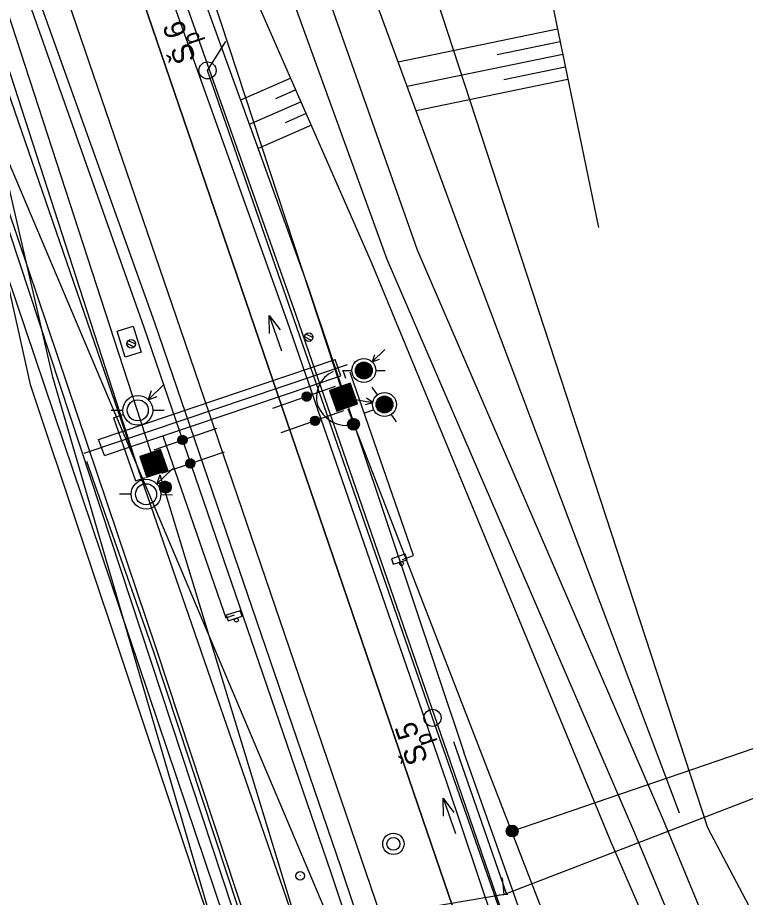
# Model space of a CAD drawing. Extents: x -439815 to -439102, y -1131353 to -1129707.
# Drawn here: x -439341.3 to -439298.8, y -1130686.6 to -1130635.3 of the extents above; entities that cross this region are included whole.
import ezdxf

# ---------------------------------------------------------------- set-up
doc = ezdxf.new("R2010")
doc.units = 0
for name, color, linetype in [('Level 1', 7, 'Continuous'), ('Level 10', 7, 'Continuous'), ('Level 11', 7, 'Continuous'), ('Level 14', 7, 'Continuous'), ('Level 15', 7, 'Continuous'), ('Level 2', 7, 'Continuous'), ('Level 20', 7, 'Continuous'), ('Level 36', 7, 'Continuous'), ('Level 4', 7, 'Continuous'), ('Level 42', 7, 'Continuous'), ('Level 48', 7, 'Continuous'), ('Level 49', 7, 'Continuous'), ('Level 5', 7, 'Continuous'), ('Level 57', 7, 'Continuous'), ('Level 59', 7, 'Continuous'), ('Level 6', 7, 'Continuous'), ('Level 61', 7, 'Continuous'), ('Level 62', 7, 'Continuous'), ('Level 63', 7, 'Continuous'), ('Level 7', 7, 'Continuous'), ('Level 9', 7, 'Continuous')]:
    doc.layers.add(name, color=color, linetype=linetype)

# ---------------------------------------------------------------- blocks, each defined once
blk = doc.blocks.new('KOTV_T')
at = {"layer": 'Level 1'}
for p, q in [((-3.44, -0.33), (0.33, 3.44)), ((-3.42, 0.47), (-0.47, 3.42)), ((-3.31, -0.98), (0.98, 3.31)), ((-3.09, -1.54), (1.54, 3.09)), ((-3.06, 1.61), (-1.61, 3.06)), ((-2.8, -2.02), (2.02, 2.8)), ((-2.44, -2.44), (2.44, 2.44)), ((-2.02, -2.8), (2.8, 2.02)), ((-1.54, -3.09), (3.09, 1.54)), ((-0.98, -3.31), (3.31, 0.98)), ((-0.33, -3.44), (3.44, 0.33)), ((0.47, -3.42), (3.42, -0.47)), ((1.61, -3.06), (3.06, -1.61))]:
    blk.add_line(p, q, dxfattribs=at)
blk.add_circle((0, 0), 3.45, dxfattribs=at)
blk = doc.blocks.new('ST1K_K')
at = {"layer": 'Level 1'}
for p, q in [((0, 0), (45.31, 0)), ((20.84, -3.13), (17.41, 0.3)), ((21.43, -3.01), (17.53, 0.89)), ((21.94, -2.81), (17.73, 1.4)), ((22.38, -2.55), (17.99, 1.84)), ((22.76, -2.22), (18.32, 2.22)), ((23.08, -1.84), (18.7, 2.55)), ((23.35, -1.4), (19.14, 2.81)), ((23.55, -0.89), (19.65, 3.01)), ((23.67, -0.3), (20.24, 3.13)), ((23.65, 0.42), (20.96, 3.11)), ((23.32, 1.46), (22, 2.78)), ((20.12, -3.11), (17.43, -0.42)), ((19.07, -2.78), (17.76, -1.46))]:
    blk.add_line(p, q, dxfattribs=at)
blk.add_circle((20.54, 0), 3.14, dxfattribs=at)
blk = doc.blocks.new('ST_BP')
at = {"layer": 'Level 1'}
for p, q in [((7.5, 7.5), (-7.5, 7.5)), ((-7.5, 7.5), (-7.5, -7.5)), ((-7.5, -7.5), (7.5, 7.5)), ((-7.5, -7.08), (7.08, 7.5)), ((-7.5, -6.65), (6.65, 7.5)), ((-7.5, -6.23), (6.23, 7.5)), ((-7.5, -5.8), (5.8, 7.5)), ((-7.5, -5.38), (5.38, 7.5)), ((-7.5, -4.95), (4.95, 7.5)), ((-7.5, -4.53), (4.53, 7.5)), ((-7.5, -4.11), (4.11, 7.5)), ((-7.5, -3.68), (3.68, 7.5)), ((-7.5, -3.26), (3.26, 7.5)), ((-7.5, -2.83), (2.83, 7.5)), ((-7.5, -2.41), (2.41, 7.5)), ((-7.5, -1.98), (1.98, 7.5)), ((-7.5, -1.56), (1.56, 7.5)), ((-7.5, -1.14), (1.14, 7.5)), ((-7.5, -0.71), (0.71, 7.5)), ((-7.5, -0.29), (0.29, 7.5)), ((-7.5, 0.14), (-0.14, 7.5)), ((-7.5, 0.56), (-0.56, 7.5)), ((-7.5, 0.99), (-0.99, 7.5)), ((-7.5, 1.41), (-1.41, 7.5)), ((-7.5, 1.83), (-1.83, 7.5)), ((-7.5, 2.26), (-2.26, 7.5)), ((-7.5, 2.68), (-2.68, 7.5)), ((-7.5, 3.11), (-3.11, 7.5)), ((-7.5, 3.53), (-3.53, 7.5)), ((-7.5, 3.96), (-3.96, 7.5)), ((-7.5, 4.38), (-4.38, 7.5)), ((-7.5, 4.8), (-4.8, 7.5)), ((-7.5, 5.23), (-5.23, 7.5)), ((-7.5, 5.65), (-5.65, 7.5)), ((-7.5, 6.08), (-6.08, 7.5)), ((-7.5, 6.5), (-6.5, 7.5)), ((-7.5, 6.92), (-6.92, 7.5)), ((-7.5, 7.35), (-7.35, 7.5)), ((-7.08, -7.5), (7.5, 7.08)), ((-6.65, -7.5), (7.5, 6.65)), ((-6.23, -7.5), (7.5, 6.23)), ((7.5, -7.5), (7.5, 7.5)), ((-5.8, -7.5), (7.5, 5.8)), ((-5.38, -7.5), (7.5, 5.38)), ((-4.95, -7.5), (7.5, 4.95)), ((-4.53, -7.5), (7.5, 4.53)), ((-4.11, -7.5), (7.5, 4.11)), ((-3.68, -7.5), (7.5, 3.68)), ((-3.26, -7.5), (7.5, 3.26)), ((-2.83, -7.5), (7.5, 2.83)), ((-2.41, -7.5), (7.5, 2.41)), ((-1.98, -7.5), (7.5, 1.98)), ((-1.56, -7.5), (7.5, 1.56)), ((-1.14, -7.5), (7.5, 1.14)), ((-0.71, -7.5), (7.5, 0.71)), ((-0.29, -7.5), (7.5, 0.29)), ((0.14, -7.5), (7.5, -0.14)), ((0.56, -7.5), (7.5, -0.56)), ((0.99, -7.5), (7.5, -0.99)), ((1.41, -7.5), (7.5, -1.41)), ((1.83, -7.5), (7.5, -1.83)), ((2.26, -7.5), (7.5, -2.26)), ((2.68, -7.5), (7.5, -2.68)), ((3.11, -7.5), (7.5, -3.11)), ((3.53, -7.5), (7.5, -3.53)), ((3.96, -7.5), (7.5, -3.96)), ((4.38, -7.5), (7.5, -4.38)), ((4.8, -7.5), (7.5, -4.8)), ((5.23, -7.5), (7.5, -5.23)), ((5.65, -7.5), (7.5, -5.65)), ((-7.5, -7.5), (7.5, -7.5)), ((6.08, -7.5), (7.5, -6.08)), ((6.5, -7.5), (7.5, -6.5)), ((6.92, -7.5), (7.5, -6.92)), ((7.35, -7.5), (7.5, -7.35))]:
    blk.add_line(p, q, dxfattribs=at)

msp = doc.modelspace()

# ---------------------------------------------------------------- linework, layer by layer
at = {"layer": 'Level 10'}
for p, q in [((-439309.738, -1130635.982), (-439319.036, -1130637.898)), ((-439309.588, -1130636.718), (-439313.262, -1130637.474)), ((-439309.436, -1130637.452), (-439318.514, -1130639.322)), ((-439309.286, -1130638.186), (-439312.872, -1130638.926)), ((-439325.316, -1130638.834), (-439328.242, -1130640.118)), ((-439309.134, -1130638.922), (-439317.992, -1130640.746)), ((-439325.014, -1130639.522), (-439326.204, -1130640.044)), ((-439324.712, -1130640.21), (-439327.732, -1130641.534)), ((-439324.412, -1130640.896), (-439325.636, -1130641.434)), ((-439324.11, -1130641.582), (-439327.22, -1130642.946))]:
    msp.add_line(p, q, dxfattribs=at)
at = {"layer": 'Level 11'}
for points in [[(-439303.556, -1130682.146), (-439317.916, -1130648.878), (-439327.804, -1130620.82), (-439331.376, -1130615.792)], [(-439331.216, -1130618.836), (-439329.76, -1130621.648), (-439319.704, -1130649.398), (-439305.298, -1130682.74)], [(-439290.368, -1130714.13), (-439303.556, -1130682.146)], [(-439305.298, -1130682.74), (-439291.93, -1130714.86)]]:
    msp.add_lwpolyline(points, dxfattribs=at)
at = {"layer": 'Level 14'}
msp.add_lwpolyline([(-439335.44, -1130653.596), (-439334.502, -1130653.304), (-439334.034, -1130654.828), (-439334.97, -1130655.116), (-439335.44, -1130653.596)], dxfattribs=at)
at = {"layer": 'Level 15'}
for p, q in [((-439324.102, -1130654.142), (-439324.512, -1130653.94)), ((-439324.016, -1130653.974), (-439324.432, -1130653.77)), ((-439334.46, -1130654.528), (-439334.87, -1130654.328)), ((-439334.374, -1130654.362), (-439334.79, -1130654.158))]:
    msp.add_line(p, q, dxfattribs=at)
for centre in [(-439334.622, -1130654.34), (-439324.264, -1130653.954)]:
    msp.add_circle(centre, 0.25, dxfattribs=at)
at = {"layer": 'Level 2'}
for centre, radius, start, end in [((-439322.18, -1130657.459), 1.636, 113.691, 198.3072), ((-439322.18, -1130657.459), 1.636, 113.691, 198.3072), ((-439321.987, -1130657.207), 1.907, 203.6959, 268.8931), ((-439321.987, -1130657.207), 1.907, 203.6959, 268.8931)]:
    msp.add_arc(centre, radius, start, end, dxfattribs=at)
at = {"layer": 'Level 20'}
for points in [[(-439317.356, -1130682.842), (-439326.906, -1130654.872), (-439337.798, -1130622.974), (-439339.224, -1130618.794), (-439340.706, -1130614.468), (-439349.146, -1130589.75), (-439360.302, -1130557.13), (-439371.172, -1130525.358), (-439381.62, -1130494.81), (-439392.342, -1130463.488), (-439403.314, -1130431.488), (-439413.424, -1130401.962), (-439423.826, -1130371.538), (-439434.464, -1130340.548), (-439445.064, -1130309.558), (-439445.462, -1130308.388), (-439447.35, -1130302.89), (-439457.16, -1130275.562)], [(-439321.24, -1130684.25), (-439331.724, -1130653.514), (-439341.682, -1130624.428), (-439343.148, -1130620.102), (-439344.652, -1130615.74), (-439353.044, -1130591.112), (-439364.316, -1130558.138), (-439374.988, -1130526.952), (-439385.508, -1130496.17), (-439396.186, -1130464.956), (-439407.226, -1130432.678), (-439417.232, -1130403.478), (-439427.682, -1130373.028), (-439438.464, -1130341.588), (-439448.942, -1130311.012), (-439450.914, -1130305.246), (-439460.972, -1130277.082)], [(-439269.22, -1130818.812), (-439281.814, -1130783.396), (-439292.526, -1130753.502), (-439304.678, -1130719.318), (-439314.858, -1130690.108), (-439317.356, -1130682.842)], [(-439286.854, -1130785.132), (-439297.084, -1130755.104), (-439308.786, -1130720.798), (-439319.098, -1130690.52), (-439321.24, -1130684.25)]]:
    msp.add_lwpolyline(points, dxfattribs=at)
at = {"layer": 'Level 36'}
for p, q in [((-439322.55, -1130616.62), (-439300.99, -1130682.56)), ((-439323.66, -1130704.2), (-439346.85, -1130635.55)), ((-439300.99, -1130682.56), (-439292.55, -1130698.49))]:
    msp.add_line(p, q, dxfattribs=at)
at = {"layer": 'Level 4'}
for points in [[(-439316.204, -1130679.942), (-439325.518, -1130652.992), (-439336.244, -1130623.018), (-439338.082, -1130617.638)], [(-439315.982, -1130678.73), (-439324.99, -1130652.666), (-439335.578, -1130622.688), (-439337.526, -1130617.51)], [(-439322.95, -1130685.206), (-439333.858, -1130653.394), (-439343.59, -1130625.92), (-439345.752, -1130619.412)], [(-439322.368, -1130684.93), (-439333.25, -1130653.118), (-439343.108, -1130625.602), (-439345.194, -1130619.284)], [(-439280.01, -1130783.522), (-439290.374, -1130752.75), (-439302.642, -1130717.624), (-439315.982, -1130678.73)], [(-439280.01, -1130783.522), (-439291.102, -1130753.178), (-439303.358, -1130718.188), (-439316.204, -1130679.942)], [(-439237.656, -1130937.666), (-439241, -1130926.51), (-439249.718, -1130901.172), (-439258.406, -1130875.05), (-439266.76, -1130849.346), (-439276.348, -1130820.732), (-439289.274, -1130782.246), (-439298.276, -1130755.542), (-439309.968, -1130722.042), (-439322.368, -1130684.93)], [(-439237.656, -1130937.666), (-439241.95, -1130926.674), (-439250.188, -1130901.72), (-439259.018, -1130875.526), (-439267.634, -1130849.508), (-439276.91, -1130821.49), (-439290.192, -1130781.67), (-439298.758, -1130756.05), (-439310.466, -1130722.552), (-439322.95, -1130685.206)]]:
    msp.add_lwpolyline(points, dxfattribs=at)
at = {"layer": 'Level 42'}
for points in [[(-439395.105, -1130455.427), (-439392.342, -1130463.488), (-439381.62, -1130494.81), (-439371.172, -1130525.358), (-439360.302, -1130557.13), (-439349.146, -1130589.75), (-439340.706, -1130614.468), (-439339.224, -1130618.794), (-439337.798, -1130622.974), (-439326.906, -1130654.872), (-439317.356, -1130682.842)], [(-439321.24, -1130684.25), (-439331.724, -1130653.514), (-439341.682, -1130624.428), (-439343.148, -1130620.102), (-439344.652, -1130615.74), (-439353.044, -1130591.112), (-439364.316, -1130558.138), (-439374.988, -1130526.952), (-439385.508, -1130496.17), (-439396.186, -1130464.956), (-439399.158, -1130456.267)], [(-439317.356, -1130682.842), (-439314.858, -1130690.108), (-439304.678, -1130719.318), (-439294.356, -1130748.353)], [(-439299.143, -1130749.065), (-439308.786, -1130720.798), (-439319.098, -1130690.52), (-439321.24, -1130684.25)]]:
    msp.add_lwpolyline(points, dxfattribs=at)
at = {"layer": 'Level 48'}
msp.add_line((-439330.171, -1130638.383), (-439329.092, -1130636.695), dxfattribs=at)
msp.add_lwpolyline([(-439273.977, -1130800.586), (-439287.398, -1130761.145), (-439303.815, -1130713.917), (-439317.04, -1130676.167), (-439330.171, -1130638.383)], dxfattribs=at)
for centre in [(-439330.171, -1130638.383), (-439317.04, -1130676.167)]:
    msp.add_circle(centre, 0.5, dxfattribs=at)
at = {"layer": 'Level 49'}
for p, q in [((-439326.571, -1130652.681), (-439325.854, -1130654.756)), ((-439316.418, -1130680.852), (-439315.701, -1130682.928))]:
    msp.add_line(p, q, dxfattribs=at)
for points in [[(-439326.552, -1130653.732), (-439326.571, -1130652.681), (-439325.937, -1130653.52)], [(-439316.399, -1130681.904), (-439316.418, -1130680.852), (-439315.785, -1130681.691)]]:
    msp.add_lwpolyline(points, dxfattribs=at)
at = {"layer": 'Level 5'}
msp.add_lwpolyline([(-439277.797, -1130823.31), (-439296.36, -1130772.17), (-439314.646, -1130718.277), (-439334.211, -1130661.631), (-439352.883, -1130603.988)], dxfattribs=at)
at = {"layer": 'Level 57'}
for p, q in [((-439300.573, -1130713.355), (-439321.952, -1130658.15)), ((-439315.693, -1130718.482), (-439332.927, -1130662.012)), ((-439312.411, -1130682.787), (-439281.025, -1130672.03))]:
    msp.add_line(p, q, dxfattribs=at)
at = {"layer": 'Level 59'}
for p, q in [((-439322.958, -1130688.178), (-439346.578, -1130632.414)), ((-439315.822, -1130677.544), (-439312.712, -1130686.468)), ((-439312.712, -1130686.468), (-439322.958, -1130688.178))]:
    msp.add_line(p, q, dxfattribs=at)
msp.add_lwpolyline([(-439240.615, -1130935.08), (-439245.006, -1130936.575), (-439254.477, -1130905.195), (-439274.831, -1130847.058), (-439298.026, -1130780.807), (-439307.773, -1130752.965), (-439314.372, -1130732.153), (-439325.758, -1130696.243), (-439342.929, -1130644.213), (-439353.367, -1130615.721)], dxfattribs=at)
at = {"layer": 'Level 6'}
for p, q in [((-439312.884, -1130686.484), (-439276.288, -1130672.354)), ((-439312.972, -1130685.498), (-439312.884, -1130686.484)), ((-439313.134, -1130686.506), (-439312.636, -1130686.462))]:
    msp.add_line(p, q, dxfattribs=at)
at = {"layer": 'Level 61'}
for p, q in [((-439322.281, -1130657.205), (-439341.23, -1130599.505)), ((-439352.156, -1130603.174), (-439333.292, -1130661.29))]:
    msp.add_line(p, q, dxfattribs=at)
at = {"layer": 'Level 62'}
msp.add_line((-439334.327, -1130661.321), (-439354.141, -1130603.913), dxfattribs=at)
at = {"layer": 'Level 63'}
for p, q in [((-439337.379, -1130660.728), (-439322, -1130655.537)), ((-439336.54, -1130659.917), (-439322.722, -1130655.253)), ((-439322.397, -1130656.198), (-439322.722, -1130655.253)), ((-439321.46, -1130655.63), (-439320.64, -1130655.63)), ((-439321.41, -1130655.565), (-439320.689, -1130655.565)), ((-439321.328, -1130655.499), (-439320.771, -1130655.499)), ((-439321.214, -1130655.434), (-439320.886, -1130655.434)), ((-439322.094, -1130656.36), (-439322.257, -1130655.887)), ((-439318.154, -1130666.701), (-439321.84, -1130656.011)), ((-439321.541, -1130655.893), (-439320.558, -1130655.893)), ((-439321.525, -1130655.827), (-439320.575, -1130655.827)), ((-439321.525, -1130655.958), (-439320.575, -1130655.958)), ((-439321.509, -1130655.761), (-439320.591, -1130655.761)), ((-439321.509, -1130656.024), (-439320.591, -1130656.024)), ((-439321.492, -1130655.696), (-439320.608, -1130655.696)), ((-439321.492, -1130656.089), (-439320.608, -1130656.089)), ((-439321.46, -1130656.155), (-439320.64, -1130656.155)), ((-439336.192, -1130660.855), (-439322.397, -1130656.198)), ((-439321.41, -1130656.22), (-439320.689, -1130656.22)), ((-439321.328, -1130656.286), (-439320.771, -1130656.286)), ((-439321.214, -1130656.351), (-439320.886, -1130656.351)), ((-439319.823, -1130658.367), (-439320.293, -1130657.696)), ((-439319.751, -1130658.357), (-439320.258, -1130657.632)), ((-439319.687, -1130658.332), (-439320.214, -1130657.581)), ((-439319.624, -1130658.308), (-439320.169, -1130657.53)), ((-439319.561, -1130658.284), (-439320.125, -1130657.479)), ((-439319.517, -1130658.233), (-439320.062, -1130657.455)), ((-439319.473, -1130658.182), (-439319.999, -1130657.431)), ((-439319.428, -1130658.131), (-439319.936, -1130657.406)), ((-439319.394, -1130658.067), (-439319.863, -1130657.396)), ((-439319.368, -1130657.989), (-439319.782, -1130657.398)), ((-439319.361, -1130657.884), (-439319.681, -1130657.428)), ((-439319.373, -1130657.753), (-439319.561, -1130657.484)), ((-439321.029, -1130658.386), (-439320.434, -1130658.181)), ((-439320.006, -1130658.335), (-439320.325, -1130657.879)), ((-439319.905, -1130658.365), (-439320.318, -1130657.774)), ((-439320.125, -1130658.279), (-439320.313, -1130658.01)), ((-439335.649, -1130658.654), (-439335.093, -1130658.462)), ((-439336.192, -1130660.855), (-439336.54, -1130659.917)), ((-439334.379, -1130662.341), (-439333.793, -1130662.139)), ((-439318.797, -1130666.923), (-439318.154, -1130666.701))]:
    msp.add_line(p, q, dxfattribs=at)
for points in [[(-439292.524, -1130791.32), (-439307.367, -1130752.78), (-439315.541, -1130727.251), (-439322.482, -1130704.449), (-439333.14, -1130672.167), (-439347.586, -1130629.381), (-439352.159, -1130615.872), (-439360.579, -1130591.518), (-439378.343, -1130536.883), (-439390.124, -1130502.75), (-439400.777, -1130471.095), (-439412.393, -1130437.172), (-439439.873, -1130358.662), (-439450.355, -1130327.185), (-439449.866, -1130322.123), (-439455.753, -1130305.502), (-439457.3, -1130298.85), (-439459.497, -1130292.207)], [(-439319.821, -1130654.664), (-439320.557, -1130655.399)], [(-439320.421, -1130654.983), (-439320.557, -1130655.399)], [(-439320.557, -1130655.399), (-439320.141, -1130655.244)], [(-439322.289, -1130655.893), (-439321.746, -1130655.893)], [(-439320.354, -1130655.893), (-439319.811, -1130655.893)], [(-439332.705, -1130656.685), (-439333.625, -1130657.605)], [(-439333.455, -1130657.084), (-439333.625, -1130657.605)], [(-439320.243, -1130657.311), (-439320.554, -1130656.867)], [(-439333.625, -1130657.605), (-439333.105, -1130657.41)], [(-439321.555, -1130657.58), (-439320.53, -1130657.76)], [(-439320.53, -1130657.76), (-439320.896, -1130657.509)], [(-439335.79, -1130658.221), (-439335.112, -1130658.221)], [(-439333.371, -1130658.221), (-439332.693, -1130658.221)], [(-439320.949, -1130657.888), (-439320.53, -1130657.76)], [(-439335.649, -1130658.654), (-439334.379, -1130662.341)], [(-439319.133, -1130658.896), (-439319.444, -1130658.452)], [(-439332.774, -1130659.701), (-439329.416, -1130669.439), (-439329.105, -1130670.34), (-439328.594, -1130670.164)], [(-439229.706, -1130961.083), (-439234.319, -1130947.462), (-439238.472, -1130936.844), (-439247.924, -1130921.561), (-439263.264, -1130880.523), (-439279.451, -1130829.598), (-439292.591, -1130791.38), (-439307.551, -1130752.883), (-439315.726, -1130727.354), (-439322.667, -1130704.552), (-439333.324, -1130672.27), (-439337.219, -1130661.201)], [(-439332.196, -1130661.609), (-439333.132, -1130662.512)], [(-439332.953, -1130661.995), (-439333.132, -1130662.512)], [(-439333.132, -1130662.512), (-439332.608, -1130662.327)], [(-439335.307, -1130663.091), (-439334.629, -1130663.103)], [(-439332.889, -1130663.133), (-439332.211, -1130663.145)]]:
    msp.add_lwpolyline(points, dxfattribs=at)
for points in [[(-439319.338, -1130667.202), (-439318.524, -1130666.942), (-439318.626, -1130666.622), (-439319.44, -1130666.882)], [(-439328.971, -1130670.503), (-439328.157, -1130670.243), (-439328.259, -1130669.923), (-439329.073, -1130670.182)]]:
    msp.add_lwpolyline(points, close=True, dxfattribs=at)
for centre, radius in [((-439321.05, -1130655.893), 0.701), ((-439321.05, -1130655.893), 0.492), ((-439319.843, -1130657.882), 0.701), ((-439334.241, -1130658.221), 0.87), ((-439334.241, -1130658.221), 0.614), ((-439319.843, -1130657.882), 0.492), ((-439333.759, -1130663.118), 0.87), ((-439333.759, -1130663.118), 0.614), ((-439318.848, -1130667.167), 0.114), ((-439328.481, -1130670.468), 0.114)]:
    msp.add_circle(centre, radius, dxfattribs=at)
at = {"layer": 'Level 7'}
msp.add_line((-439324.748, -1130685.414), (-439324.764, -1130685.366), dxfattribs=at)
for centre, radius in [((-439319.32, -1130683.522), 0.623), ((-439319.32, -1130683.522), 0.376), ((-439324.757, -1130685.39), 0.25)]:
    msp.add_circle(centre, radius, dxfattribs=at)
at = {"layer": 'Level 9'}
for points in [[(-439302.616, -1130681.722), (-439315.394, -1130647.836), (-439325.592, -1130620.022), (-439330.646, -1130613.072), (-439326.982, -1130606.17), (-439310.098, -1130596.386)], [(-439304.064, -1130603.548), (-439312.168, -1130612.528), (-439313.262, -1130618.886), (-439307.358, -1130647.542)], [(-439337.526, -1130617.51), (-439334.41, -1130623.048), (-439324.342, -1130650.912), (-439315.202, -1130678.168)], [(-439337.526, -1130617.51), (-439332.438, -1130622.598), (-439320.59, -1130649.608), (-439306.658, -1130683.374)], [(-439329.016, -1130691.134), (-439339.192, -1130656.276), (-439343.888, -1130636.026), (-439354.284, -1130638.834)], [(-439353.788, -1130640.606), (-439344.68, -1130638.07), (-439340.524, -1130656.706), (-439329.016, -1130691.134)], [(-439225.732, -1130933.398), (-439229.604, -1130923.888), (-439239.092, -1130898.916), (-439247.79, -1130873.56), (-439257.606, -1130845.04), (-439266.65, -1130817.146), (-439278.574, -1130785.616), (-439289.83, -1130752.464), (-439300.562, -1130719.612), (-439315.202, -1130678.168)], [(-439306.658, -1130683.374), (-439292.824, -1130715.24)]]:
    msp.add_lwpolyline(points, dxfattribs=at)

# ---------------------------------------------------------------- block references
at = {"layer": 'Level 2'}
for name, p, xscale, yscale, rotation in [('ST1K_K', (-439322.729, -1130656.839), 0.08533299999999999, 0.08533300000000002, -160.83699069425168), ('ST1K_K', (-439322.729, -1130656.839), 0.08533299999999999, 0.08533300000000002, -160.83699069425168), ('ST_BP', (-439322.236, -1130657.456), 0.085333, 0.08533300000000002, -160.83370949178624), ('ST_BP', (-439322.236, -1130657.456), 0.085333, 0.08533300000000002, -160.83370949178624), ('ST1K_K', (-439322.236, -1130658.256), 0.08533300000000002, 0.08533300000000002, -160.83037784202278), ('ST1K_K', (-439322.236, -1130658.256), 0.08533300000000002, 0.08533300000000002, -160.83037784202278), ('ST1K_K', (-439333.289, -1130660.521), 0.08533300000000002, 0.085333, 18.917487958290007), ('ST1K_K', (-439333.289, -1130660.521), 0.08533300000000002, 0.085333, 18.917487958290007), ('ST_BP', (-439333.305, -1130661.313), 0.085333, 0.085333, 18.91748967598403), ('ST_BP', (-439333.305, -1130661.313), 0.085333, 0.085333, 18.91748967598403), ('ST1K_K', (-439332.829, -1130661.893), 0.085333, 0.08533300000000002, 18.91748795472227), ('ST1K_K', (-439332.829, -1130661.893), 0.085333, 0.08533300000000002, 18.91748795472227)]:
    msp.add_blockref(name, p, dxfattribs=dict(at, xscale=xscale, yscale=yscale, rotation=rotation))
at = {"layer": 'Level 57', "xscale": 0.10000000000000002, "yscale": 0.1, "rotation": 1}
for p in [(-439321.647, -1130659.036), (-439332.632, -1130662.706), (-439312.389, -1130682.777)]:
    msp.add_blockref('KOTV_T', p, dxfattribs=at)

# ---------------------------------------------------------------- texts
at = {"layer": 'Level 49'}
for s, height, p in [('Š 6', 1.25, (-439330.824, -1130637.745)), ('p', 0.938, (-439330.545, -1130636.703)), ('Š 5', 1.25, (-439317.278, -1130678.664)), ('p', 0.938, (-439316.999, -1130677.622))]:
    msp.add_text(s, height=height, rotation=108.9175, dxfattribs=at).set_placement(p)

doc.saveas('drawing.dxf')
